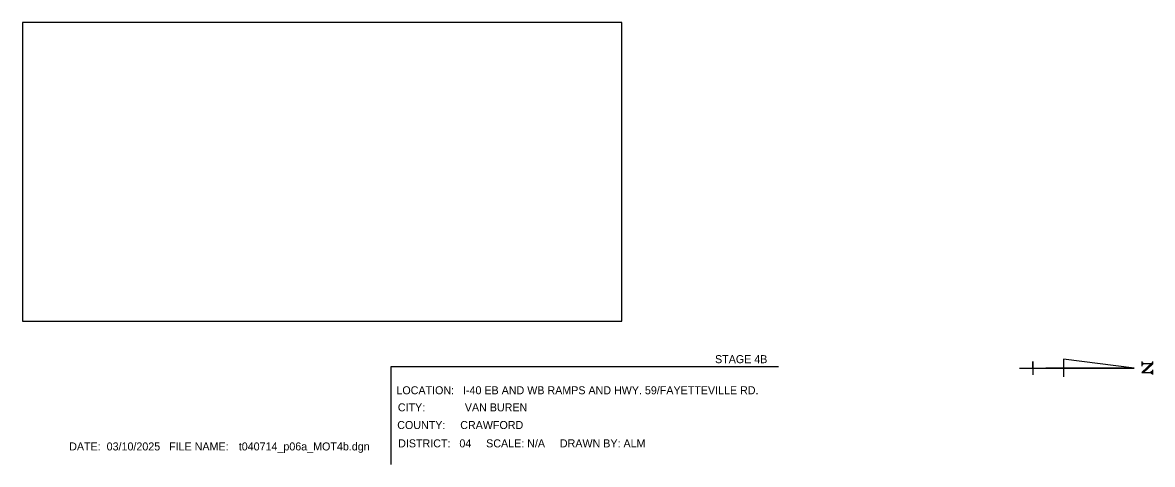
# Model space of a CAD drawing. Extents: x -218554 to 420030, y -565899 to -483460.
# Drawn here: x 419437 to 420030, y -565899 to -565667 of the extents above; entities that cross this region are included whole.
import ezdxf

# ---------------------------------------------------------------- set-up
doc = ezdxf.new("R2010")
doc.units = 0
for name, color, linetype in [('Level 1', 7, 'Continuous'), ('Level 10', 7, 'Continuous'), ('Level 57', 7, 'Continuous'), ('No Plot', 7, 'Continuous')]:
    doc.layers.add(name, color=color, linetype=linetype)

msp = doc.modelspace()

# ---------------------------------------------------------------- linework, layer by layer
at = {"layer": 'Level 1'}
for p, q in [((419960.61, -565848.23), (420020.9, -565848.24)), ((419960.61, -565848.23), (419974.52, -565848.23)), ((419960.61, -565848.23), (419967.56, -565848.23)), ((419967.56, -565848.23), (419967.56, -565844.75)), ((419967.56, -565844.75), (419967.56, -565851.71)), ((420020.9, -565848.24), (419974.52, -565848.23)), ((419983.8, -565843.6), (419983.79, -565852.87)), ((420020.9, -565848.24), (419983.8, -565843.6))]:
    msp.add_line(p, q, dxfattribs=at)
for points in [[(420024.77, -565844.84), (420024.77, -565847.25)], [(420030.4, -565845.28), (420024.77, -565850.54), (420029.45, -565850.54), (420030.39, -565851.2)], [(420029.66, -565845.94), (420025.72, -565845.94), (420024.77, -565845.28)], [(420025.72, -565845.94), (420024.77, -565846.23)], [(420024.77, -565846.38), (420025.72, -565845.94), (420024.77, -565846.52)], [(420030.4, -565845.79), (420025.28, -565850.54)], [(420030.4, -565846.01), (420025.58, -565850.54)], [(420030.4, -565844.84), (420030.4, -565846.23), (420025.72, -565850.54)], [(420030.4, -565849.88), (420029.45, -565850.54), (420030.4, -565850.83)], [(420029.45, -565850.54), (420030.39, -565850.98)], [(420030.39, -565849.23), (420030.4, -565851.64)]]:
    msp.add_lwpolyline(points, dxfattribs=at)
at = {"layer": 'Level 57'}
for points in [[(419630.59, -565847.55), (419630.59, -565898.75)], [(419834.17, -565847.55), (419630.59, -565847.55)]]:
    msp.add_lwpolyline(points, dxfattribs=at)
at = {"layer": 'No Plot'}
msp.add_lwpolyline([(419437.3, -565823.53), (419751.89, -565823.53), (419751.89, -565666.98), (419437.3, -565666.98)], close=True, dxfattribs=at)

# ---------------------------------------------------------------- texts
at = {"layer": 'Level 10'}
for s, p in [('STAGE 4B', (419800.81, -565845.65)), ('LOCATION:   I-40 EB AND WB RAMPS AND HWY. 59/FAYETTEVILLE RD.', (419633.55, -565861.97)), ('CITY:', (419634.29, -565870.93)), (' VAN BUREN', (419667.89, -565870.93)), ('COUNTY:     CRAWFORD', (419633.97, -565880.2)), ('DATE:  03/10/2025   FILE NAME: ', (419461.76, -565891.43)), ('t040714_p06a_MOT4b.dgn', (419550.78, -565891.43)), ('DISTRICT:   04     SCALE: N/A     DRAWN BY: ALM', (419634.46, -565889.83))]:
    msp.add_text(s, height=4.2, rotation=360, dxfattribs=at).set_placement(p)

doc.saveas('drawing.dxf')
